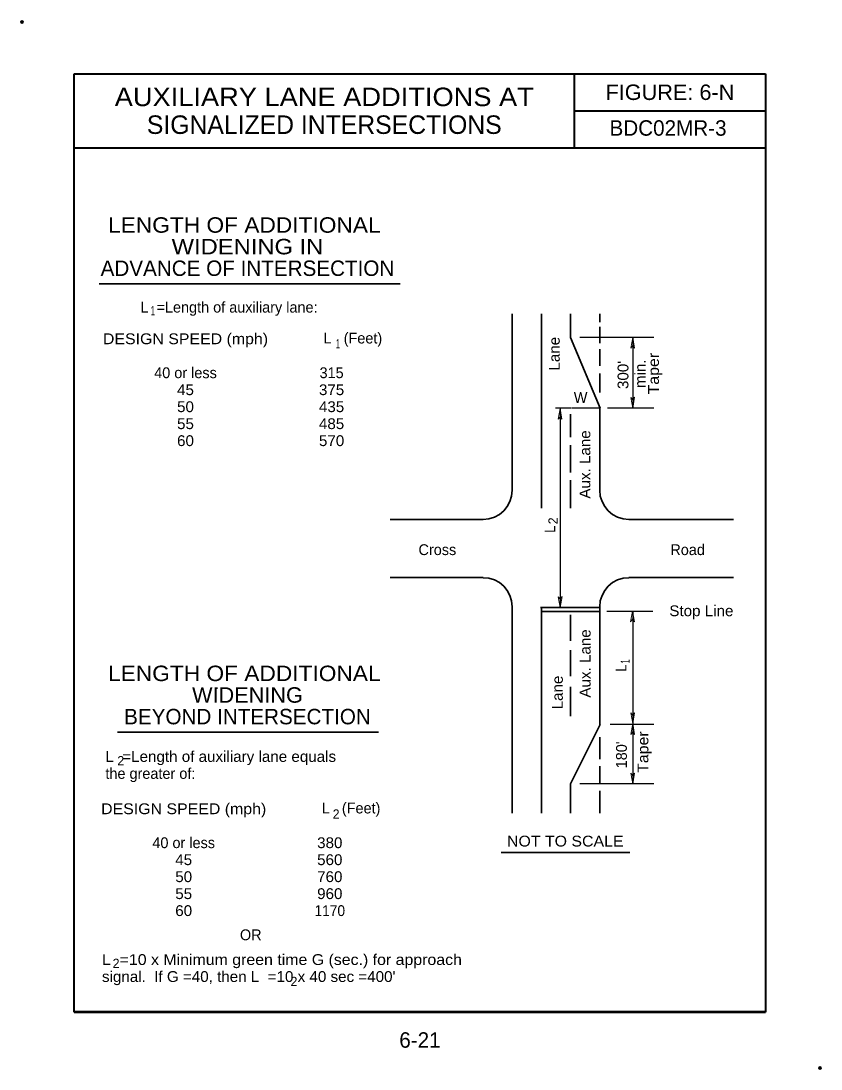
# Model space of a CAD drawing. Extents: x 0.2 to 0.875, y 0.611 to 1.495.
import ezdxf
from ezdxf.enums import TextEntityAlignment as Align

# ---------------------------------------------------------------- set-up
doc = ezdxf.new("R2010")
doc.units = 0
doc.header["$LTSCALE"] = 0.0036
doc.header["$PDMODE"] = 32
doc.header["$PDSIZE"] = 0.0018
doc.layers.add('1', color=7, linetype='Continuous', lineweight=35)

msp = doc.modelspace()

# ---------------------------------------------------------------- linework, layer by layer
at = {"layer": '1', "lineweight": 40}
for p, q in [((0.244867, 0.6593), (0.244867, 1.450967)), ((0.244867, 1.450967), (0.8282, 1.450967)), ((0.666742, 1.450967), (0.666742, 1.388467)), ((0.8282, 1.450967), (0.8282, 0.6593)), ((0.666742, 1.419717), (0.8282, 1.419717)), ((0.244867, 1.388467), (0.8282, 1.388467))]:
    msp.add_line(p, q, dxfattribs=at)
at = {"layer": '1', "lineweight": 13}
for p, q in [((0.365392, 1.31035), (0.365392, 1.311275)), ((0.365383, 0.93205), (0.365383, 0.932975))]:
    msp.add_line(p, q, dxfattribs=at)
at = {"layer": '1'}
for p, q in [((0.265925, 1.273633), (0.519883, 1.273633)), ((0.614408, 1.24845), (0.614408, 1.0996)), ((0.639017, 1.24845), (0.639017, 1.0843)), ((0.663625, 1.24845), (0.663625, 1.22855)), ((0.688242, 1.24845), (0.688242, 1.241342)), ((0.688242, 1.237433), (0.688242, 1.223758)), ((0.6885, 1.168867), (0.663625, 1.22855)), ((0.688242, 1.218675), (0.688242, 1.2046)), ((0.688242, 1.197958), (0.688242, 1.181933)), ((0.688242, 1.168867), (0.688242, 1.0996)), ((0.663625, 1.163633), (0.663625, 1.144333)), ((0.663625, 1.137558), (0.663625, 1.114542)), ((0.663625, 1.108108), (0.663625, 1.0843)), ((0.5113, 1.074992), (0.5898, 1.074992)), ((0.71285, 1.074992), (0.801033, 1.074992)), ((0.5113, 1.025783), (0.5898, 1.025783)), ((0.71285, 1.025783), (0.801033, 1.025783)), ((0.614408, 1.001167), (0.614408, 0.827025)), ((0.638375, 1.000683), (0.6876, 1.000683)), ((0.639017, 1.000683), (0.639017, 0.827025)), ((0.688242, 1.001167), (0.688242, 0.901825)), ((0.638833, 0.997308), (0.6876, 0.997308)), ((0.663625, 0.99435), (0.663625, 0.97245)), ((0.663625, 0.964692), (0.663625, 0.942792)), ((0.663625, 0.933608), (0.663625, 0.908883)), ((0.281242, 0.895333), (0.501583, 0.895333)), ((0.688242, 0.891142), (0.688242, 0.872592)), ((0.688242, 0.866775), (0.688242, 0.851758)), ((0.688242, 0.84605), (0.688242, 0.827025)), ((0.60495, 0.793825), (0.713608, 0.793825))]:
    msp.add_line(p, q, dxfattribs=at)
at = {"layer": '1', "lineweight": 25}
for p, q in [((0.733833, 1.22855), (0.671583, 1.22855)), ((0.716092, 1.22855), (0.716092, 1.168867)), ((0.663767, 1.168867), (0.6509, 1.168867)), ((0.654817, 1.168475), (0.654817, 1.000683)), ((0.688242, 1.168867), (0.664442, 1.168867)), ((0.733833, 1.168867), (0.6949, 1.168867)), ((0.733192, 0.997308), (0.694258, 0.997308)), ((0.716092, 0.997308), (0.716092, 0.902625)), ((0.716092, 0.902625), (0.716092, 0.851758)), ((0.733833, 0.901825), (0.697017, 0.901825)), ((0.733833, 0.851758), (0.671583, 0.851758))]:
    msp.add_line(p, q, dxfattribs=at)
at = {"layer": '1', "lineweight": 53}
msp.add_line((0.8282, 0.6593), (0.244867, 0.6593), dxfattribs=at)
at = {"layer": '1', "lineweight": 13}
for points in [[(0.716092, 1.22855), (0.714483, 1.21945), (0.716092, 1.221625), (0.717667, 1.2195)], [(0.716092, 1.168867), (0.7177, 1.177958), (0.716092, 1.175783), (0.714508, 1.177917)], [(0.654817, 1.168475), (0.653217, 1.159375), (0.654817, 1.16155), (0.6564, 1.159425)], [(0.654817, 1.168475), (0.653217, 1.159375), (0.654817, 1.16155), (0.6564, 1.159425)], [(0.654817, 1.000667), (0.656433, 1.009767), (0.654817, 1.007592), (0.653242, 1.009725)], [(0.715908, 0.997583), (0.7143, 0.988492), (0.715908, 0.990658), (0.717492, 0.988533)], [(0.716092, 0.902625), (0.7177, 0.911725), (0.716092, 0.90955), (0.714508, 0.911683)], [(0.716092, 0.902625), (0.7177, 0.911725), (0.716092, 0.90955), (0.714508, 0.911683)], [(0.716092, 0.902625), (0.714483, 0.893533), (0.716092, 0.895708), (0.717667, 0.893583)], [(0.716092, 0.902625), (0.714483, 0.893533), (0.716092, 0.895708), (0.717667, 0.893583)], [(0.716092, 0.851758), (0.7177, 0.86085), (0.716092, 0.858675), (0.714508, 0.860808)]]:
    msp.add_lwpolyline(points, close=True, dxfattribs=at)
at = {"layer": '1'}
msp.add_lwpolyline([(0.688542, 0.901825), (0.663625, 0.851758), (0.663625, 0.827025)], dxfattribs=at)
for centre, start, end in [((0.589801, 1.099604), 270, 0), ((0.712848, 1.099604), 180, 270), ((0.589801, 1.001167), 0, 90), ((0.712848, 1.001167), 90, 180)]:
    msp.add_arc(centre, 0.024609, start, end, dxfattribs=at)
for p in [(0.200758, 1.494592), (0.874092, 0.612092)]:
    msp.add_point(p, dxfattribs=at)

# ---------------------------------------------------------------- texts
for s, height, width, p in [('FIGURE: 6-N', 0.01303, 1.05, (0.747475, 1.428825)), ('AUXILIARY LANE ADDITIONS AT', 0.01562, 1.1, (0.455808, 1.423625)), ('LENGTH OF ADDITIONAL ', 0.01303, 1.1, (0.390996, 1.316817)), ('WIDENING IN', 0.01303, 1.15, (0.390996, 1.298583)), ('1', 0.007817, 0.6, (0.311113, 1.247083)), ('DESIGN SPEED (mph)', 0.009117, 1.1, (0.338704, 1.222758)), ('1', 0.007817, 0.6, (0.467346, 1.219292)), ('45', 0.009117, 1.05, (0.338704, 1.179783)), ('375', 0.009117, 1.05, (0.461983, 1.179783)), ('50', 0.009117, 1.05, (0.338708, 1.165458)), ('435', 0.009117, 1.05, (0.461983, 1.165458)), ('55', 0.009117, 1.05, (0.338704, 1.151133)), ('485', 0.009117, 1.05, (0.461983, 1.151133)), ('60', 0.009117, 1.05, (0.338708, 1.136808)), ('570', 0.009117, 1.05, (0.461979, 1.136808)), ('Stop Line', 0.009117, 1.05, (0.774025, 0.993283)), ('LENGTH OF ADDITIONAL ', 0.01303, 1.1, (0.390988, 0.938517)), ('WIDENING', 0.01303, 1.05, (0.390996, 0.920283)), ('DESIGN SPEED (mph)', 0.009117, 1.1, (0.337179, 0.826233)), ('380', 0.009117, 1.05, (0.460454, 0.797583)), ('NOT TO SCALE', 0.009117, 1.1, (0.659162, 0.798942)), ('45', 0.009117, 1.05, (0.337179, 0.783258)), ('560', 0.009117, 1.05, (0.460454, 0.783258)), ('50', 0.009117, 1.05, (0.337183, 0.768933)), ('760', 0.009117, 1.05, (0.460454, 0.768933)), ('55', 0.009117, 1.05, (0.337179, 0.754608)), ('960', 0.009117, 1.05, (0.460454, 0.754608)), ('60', 0.009117, 1.05, (0.337183, 0.740283)), ('1170', 0.009117, 0.95, (0.460458, 0.740283))]:
    msp.add_text(s, height=height, dxfattribs=dict(at, width=width)).set_placement(p, align=Align.CENTER)
for s, height, p in [('SIGNALIZED INTERSECTIONS', 0.01562, (0.455804, 1.400183)), ('BDC02MR-3', 0.01303, (0.745879, 1.398675)), ('ADVANCE OF INTERSECTION', 0.01303, (0.390996, 1.28035)), ('40 or less', 0.009117, (0.338704, 1.194108)), ('315', 0.009117, (0.461983, 1.194108)), ('BEYOND INTERSECTION', 0.01303, (0.390992, 0.90205)), ('2', 0.007817, (0.284042, 0.867425)), ('2', 0.007817, (0.465817, 0.822417)), ('40 or less', 0.009117, (0.337179, 0.797583)), ('2', 0.007817, (0.280092, 0.696442)), ('2', 0.007817, (0.430225, 0.681125)), ('6-21', 0.01303, (0.536533, 0.629183))]:
    msp.add_text(s, height=height, dxfattribs=at).set_placement(p, align=Align.CENTER)
for s, p in [('L  =Length of auxiliary lane:', (0.300692, 1.24945)), ('L   (Feet)', (0.455242, 1.223375)), ('W', (0.666367, 1.173208)), ('Cross', (0.535325, 1.044833)), ('Road', (0.747842, 1.044825)), ('the greater of:', (0.271133, 0.856033)), ('L   (Feet)', (0.453717, 0.82685)), ('OR', (0.38465, 0.719875))]:
    msp.add_text(s, height=0.009117, dxfattribs=at).set_placement(p)
for s, width, p in [('Lane', 1.05, (0.654483, 1.200483)), ('Taper', 1.1, (0.738192, 1.1804)), ("300'", 1.05, (0.712442, 1.184933)), ('min.', 1.05, (0.726908, 1.185708)), ('Aux. Lane', 1.05, (0.680317, 1.092458)), ('L', 0.9, (0.650767, 1.063625)), ('Taper', 1.1, (0.729292, 0.8611))]:
    msp.add_text(s, height=0.009117, rotation=90, dxfattribs=dict(at, width=width)).set_placement(p)
msp.add_text('2', height=0.007817, rotation=90, dxfattribs=at).set_placement((0.652733, 1.073725), align=Align.CENTER)
for s, height, width, p in [('Aux. Lane', 0.009117, 1.05, (0.680508, 0.953392)), ('1', 0.007817, 0.6, (0.713608, 0.955204)), ('L', 0.009117, 0.9, (0.710767, 0.949442)), ('Lane', 0.009117, 1.05, (0.657075, 0.928883))]:
    msp.add_text(s, height=height, rotation=90, dxfattribs=dict(at, width=width)).set_placement(p, align=Align.CENTER)
msp.add_text("180'", height=0.009117, rotation=90, dxfattribs=at).set_placement((0.711125, 0.864933))
for s, width, p in [('L  =Length of auxiliary lane equals', 1.05, (0.271133, 0.870358)), ('L  =10 x Minimum green time G (sec.) for approach ', 1.1, (0.268225, 0.698992)), ("signal.  If G =40, then L  =10 x 40 sec =400'", 1.05, (0.268225, 0.684667))]:
    msp.add_text(s, height=0.009117, dxfattribs=dict(at, width=width)).set_placement(p)

doc.saveas('drawing.dxf')
